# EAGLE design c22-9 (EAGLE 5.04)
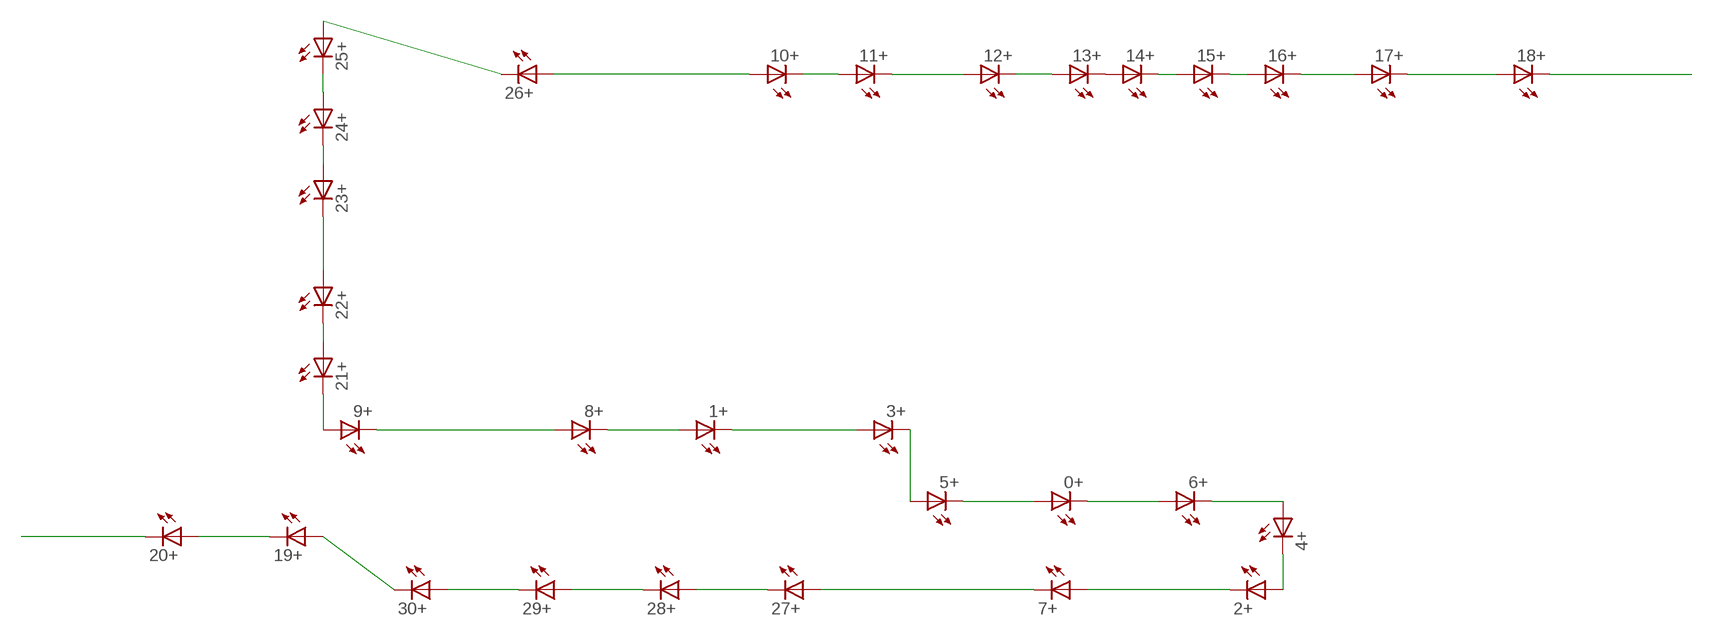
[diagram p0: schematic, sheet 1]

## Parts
0+  LED5MM  [LED5MM]
1+  LED5MM  [LED5MM]
2+  LED5MM  [LED5MM]
3+  LED5MM  [LED5MM]
4+  LED5MM  [LED5MM]
5+  LED5MM  [LED5MM]
6+  LED5MM  [LED5MM]
7+  LED5MM  [LED5MM]
8+  LED5MM  [LED5MM]
9+  LED5MM  [LED5MM]
10+  LED5MM  [LED5MM]
11+  LED5MM  [LED5MM]
12+  LED5MM  [LED5MM]
13+  LED5MM  [LED5MM]
14+  LED5MM  [LED5MM]
15+  LED5MM  [LED5MM]
16+  LED5MM  [LED5MM]
17+  LED5MM  [LED5MM]
18+  LED5MM  [LED5MM]
19+  LED5MM  [LED5MM]
20+  LED5MM  [LED5MM]
21+  LED5MM  [LED5MM]
22+  LED5MM  [LED5MM]
23+  LED5MM  [LED5MM]
24+  LED5MM  [LED5MM]
25+  LED5MM  [LED5MM]
26+  LED5MM  [LED5MM]
27+  LED5MM  [LED5MM]
28+  LED5MM  [LED5MM]
29+  LED5MM  [LED5MM]
30+  LED5MM  [LED5MM]

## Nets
MINUS: 20+.K(C)
MINUS9: 18+.K(C)
N$1: 16+.K(C) 17+.A
N$2: 19+.K(C) 20+.A
N$3: 11+.K(C) 12+.A
N$4: 19+.A 30+.K(C)
N$5: 10+.K(C) 11+.A
N$6: 8+.A 9+.K(C)
N$7: 29+.K(C) 30+.A
N$8: 28+.K(C) 29+.A
N$9: 27+.K(C) 28+.A
N$10: 14+.K(C) 15+.A
N$11: 13+.K(C) 14+.A
N$12: 2+.K(C) 7+.A
N$13: 7+.K(C) 27+.A
N$14: 2+.A 4+.K(C)
N$15: 4+.A 6+.K(C)
N$16: 0+.K(C) 6+.A
N$17: 0+.A 5+.K(C)
N$18: 3+.K(C) 5+.A
N$19: 1+.K(C) 3+.A
N$20: 1+.A 8+.K(C)
N$21: 17+.K(C) 18+.A
N$23: 9+.A 21+.K(C)
N$24: 21+.A 22+.K(C)
N$25: 22+.A 23+.K(C)
N$26: 24+.A 25+.K(C)
N$27: 25+.A 26+.K(C)
N$28: 23+.A 24+.K(C)
N$30: 15+.K(C) 16+.A
N$32: 12+.K(C) 13+.A
PLUS: 10+.A 26+.A

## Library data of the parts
0+ 1+ 2+ 3+ 4+ 5+ 6+ 7+ 8+ 9+ 10+ 11+ 12+ 13+ 14+ 15+ 16+ 17+ 18+ 19+ 20+ 21+ 22+ 23+ 24+ 25+ 26+ 27+ 28+ 29+ 30+ = led(2):LED: LED

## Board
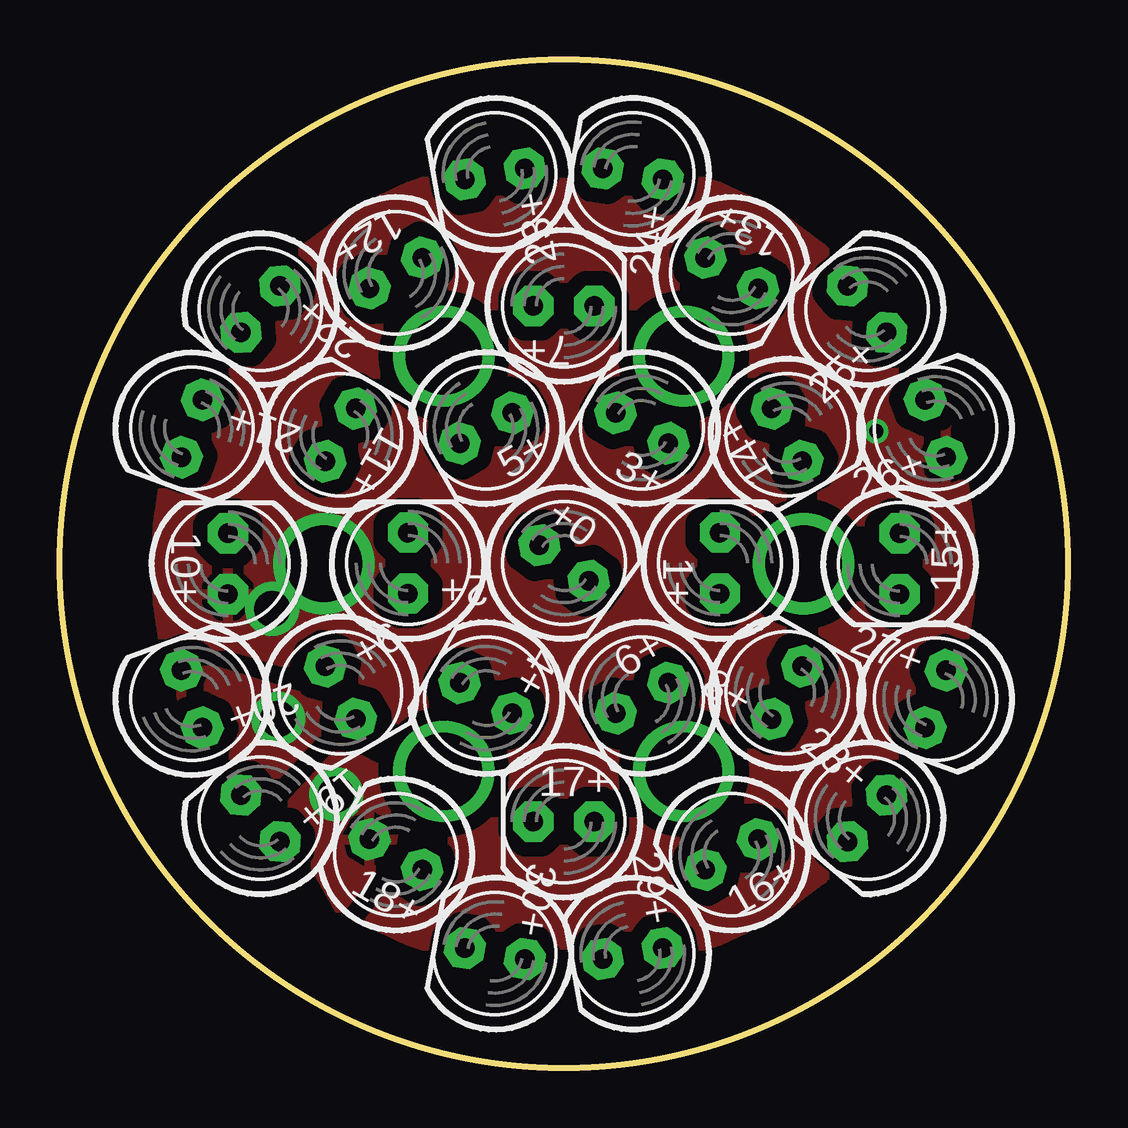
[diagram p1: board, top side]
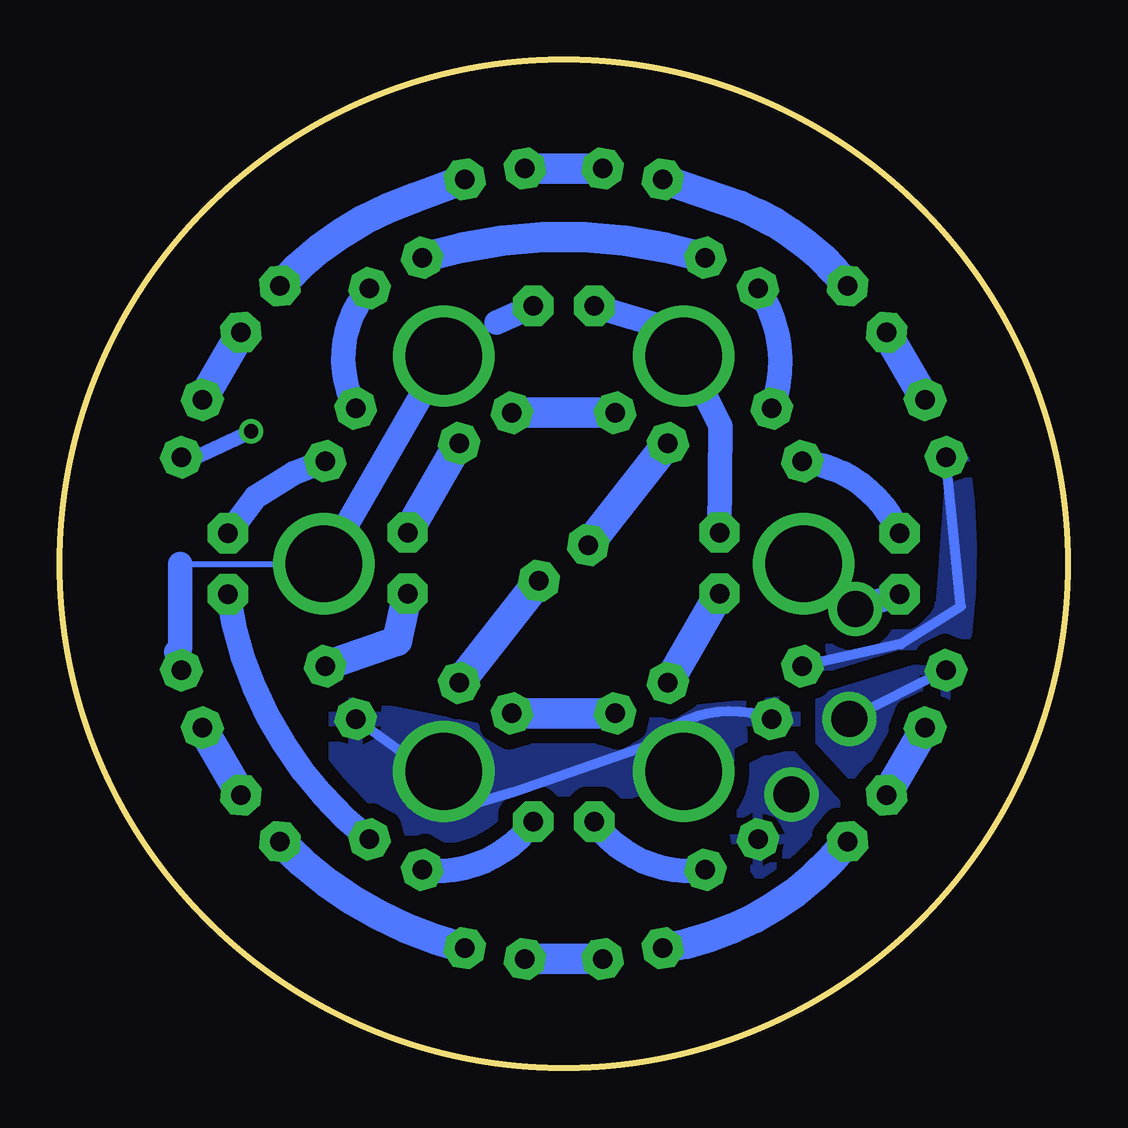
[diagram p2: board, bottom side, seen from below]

Size 42 x 42 mm. Coordinates in mm from the lower left corner, seen from the top.
Outline: circle at 21,21 radius 21
Copper layers (1*16): Top 0.035mm / dielectric 1.5mm / Bottom 0.035mm
Design rules "default": minimum track width 10mil, minimum drill 24mil, track to track 8mil, track to pad 8mil, pad to pad 8mil, via to via 8mil, smd to smd 8mil, copper to edge 40mil, drill to drill 8mil, minimum pad ring 10mil, minimum via ring 8mil, stop-mask expansion 4mil, vias tented up to drill 0mil, thermal gap 10mil

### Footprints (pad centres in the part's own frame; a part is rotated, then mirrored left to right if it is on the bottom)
LED5MM = drill 0.813 pad 1.676 octagon: A -1.27,0; K 1.27,0

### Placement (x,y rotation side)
0+  21.01,21.03 324.1 top
1+  27.51,21.03 90 top
2+  14.51,21.03 90 top
3+  24.26,26.66 150 top
4+  17.76,15.4 150 top
5+  17.76,26.66 210 top
6+  24.26,15.4 210 top
7+  21,31.75 0 top
8+  30.31,15.63 60 top
9+  11.69,15.63 300 top
10+  7,21 90 top
11+  11.69,26.37 60 top
12+  14,33.12 30 top
13+  28,33.12 330 top
14+  30.31,26.38 300 top
15+  35,21 270 top
16+  28,8.88 210 top
17+  21,10.25 180 top
18+  14,8.88 150 top
19+  8.36,10.39 130 top
20+  5.5,15.36 110 top
21+  5.5,26.64 250 top
22+  8.36,31.61 230 top
23+  18.13,37.25 190 top
24+  23.87,37.25 170 top
25+  33.64,31.61 130 top
26+  36.5,26.64 110 top
27+  36.5,15.36 250 top
28+  33.64,10.39 230 top
29+  23.87,4.75 190 top
30+  18.13,4.75 170 top

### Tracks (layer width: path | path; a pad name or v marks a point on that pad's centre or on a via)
MINUS  (via drill 1.5)
  Bottom 0.406: 20+.K v9.1,14.54
  pour Bottom (isolate 0.61, rank 3): 4.73,17.08 11.78,14.92 7.96,10.95 5.5,13.49
  pour Top (isolate 0.61, rank 3): 4.73,17.08 11.78,14.92 7.96,10.95 5.5,13.49
MINUS9  (via drill 1.5)
  other vias: 11.51,11.38
  pour Bottom (isolate 0.61): 13.81,9.28 12.63,7.7 9.34,10.68 11.71,13.26 14.27,11.93
  pour Top (isolate 0.61): 13.81,9.28 11.66,6.59 9.34,10.68 11.71,13.26 14.27,11.93
N$1
  Bottom 1.016: 17+.A arc62 16+.K
N$2
  Bottom 1.27: 19+.K 20+.A
N$3
  Bottom 1.016: 11+.K arc-54 12+.A
N$4
  Bottom 1.27: 19+.A arc42 30+.K
N$5
  Bottom 1.016: 10+.K arc-60 11+.A
N$6  (via drill 3.2)
  Bottom 0.406: 9+.K arc-66 17.42,13.45 23.12,11.47 24.65,11.02 26.45,12.2 8+.A
  other vias: 26,12.34 16,12.34
  pour Bottom (isolate 0.61, rank 2): 11.43,15.24 24.13,13.97 30.48,15.24 30.48,11.43 25.4,8.89 11.43,13.97
N$7
  Bottom 1.27: 30+.A 29+.K
N$8
  Bottom 1.27: 29+.A arc31 28+.K
N$9
  Bottom 1.27: 28+.A 27+.K
N$10
  Bottom 1.016: 14+.K 32.24,24.78 33.85,23.79 15+.A
N$11
  Bottom 1.016: 14+.A arc69 13+.K
N$12  (via drill 3.2)
  Bottom 0.406: 16.47,30.76 v16,29.66
  Bottom 1.016: 2+.K 14.46,26.75 16.47,30.76 7+.A
N$13  (via drill 3.2)
  Bottom 0.254: 23.8,31.05 v26,29.66 | 36.96,21 v31,21
  Bottom 0.406: 37.16,17.33 36.99,17.5 | 36.99,21 36.96,21
  Bottom 1.016: 7+.K 23.8,31.05 | 27+.A 37.16,17.33 | 36.99,17.5 36.99,21 | v26,29.66 v31,21
N$14
  Bottom 1.27: 4+.K 2+.A
N$15
  Bottom 1.27: 4+.A 6+.K
N$16
  Bottom 1.27: 0+.K 6+.A
N$17
  Bottom 1.27: 0+.A 5+.K
N$18
  Bottom 1.27: 5+.A 3+.K
N$19
  Bottom 1.27: 1+.K 3+.A
N$20
  Bottom 1.27: 1+.A 27.94,17.78 8+.K
N$21
  Bottom 1.016: 18+.A arc63 17+.K
N$23
  Bottom 0.406: 9+.A 6.94,17.65 4.44,19.22 21+.K
  pour Bottom (isolate 0.61, rank 4): 4.29,25.35 arc16 4.2,18.02 5.19,16.73 10.72,15.57 11.19,17.23 5.29,19.28 4.78,26.05
N$24
  Bottom 1.27: 21+.A 22+.K
N$25
  Bottom 1.27: 22+.A arc-30 13.66,35.92 23+.K
N$26
  Bottom 1.27: 24+.A 27.27,36.23 arc-30 25+.K
N$27
  Bottom 1.27: 26+.K 25+.A
N$28
  Bottom 1.27: 23+.A 24+.K
N$30
  Bottom 1.016: 16+.A arc43 15+.K
N$32
  Bottom 1.27: 12+.K arc-34 13+.A
PLUS  (via drill 0.6, 1.5, 3.2)
  Top 1.016: v8.84,19.12 v11,21
  Bottom 0.61: v34.03,26.52 37.12,25.08
  Bottom 1.016: 10+.A v8.84,19.12
  pour Top (isolate 0.61, rank 4): 21,38 arc180 21,4 arc180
